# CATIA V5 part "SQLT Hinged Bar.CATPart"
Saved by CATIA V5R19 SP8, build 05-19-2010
Part number: SQLT Hinged Bar 15
Publications: "Droite.1", "Plan.1", "Plan.2", "Droite.2", "Droite.3", "Plan.3", "Plan.4", "Point.3", "Point.4"
Bounding box of the stored display mesh (mm): x -150 to 150, y 600 to 1000, z 500 to 700
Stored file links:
  G:\EU_thinkMotion\CFAO_2010\MMS_groupe3\MMS_groupe3\A reprendre\fovide\fovide\SQLT Hinged Bar.CATPart
  G:\EU_thinkMotion\CFAO_2010\MMS_groupe3\MMS_groupe3\A reprendre\fovide\fovide\fovide.CATProduct
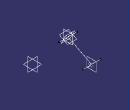
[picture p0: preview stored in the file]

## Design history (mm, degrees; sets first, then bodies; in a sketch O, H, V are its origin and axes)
Set1
  Point1 "Point.C": linked copy from another document
  Point2 "Point.D": linked copy from another document
  Plane1: linked copy from another document
Set2 "set Hinged Bar"
  Line1: type PtPt, FirstPoint Point1, SecondPoint Point2
  Plane2: type OffsetPt, RefPlane yz-plane, RefPoint Point1
  Plane3: type OffsetPt, RefPlane yz-plane, RefPoint Point2
  Line2: type Normal, RefPoint Point1, RefSkin Plane2, Start -150, End 150
  Line3: type Normal, RefPoint Point2, RefSkin Plane3, Start -150, End 150
  Plane4: type Normal, Curve Line1, RefPoint Point1
  Plane5: type Angle, RefPlane Plane4, Direction Line2, Angle 90
  Point3: type OnCurve, Support Line2, Length 122
  Point4: type OnCurve, Support Line3, Length 122
Body1 (main body)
